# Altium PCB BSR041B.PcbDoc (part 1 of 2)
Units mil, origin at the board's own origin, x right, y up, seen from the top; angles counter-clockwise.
Board outline 3820.03 x 2030.03 mil, 4 copper layers (Top Layer, MidLayer1, MidLayer2, Bottom Layer), stack 59.4 mil thick; 65 components, 15 nets, 109 pads, 61 vias.
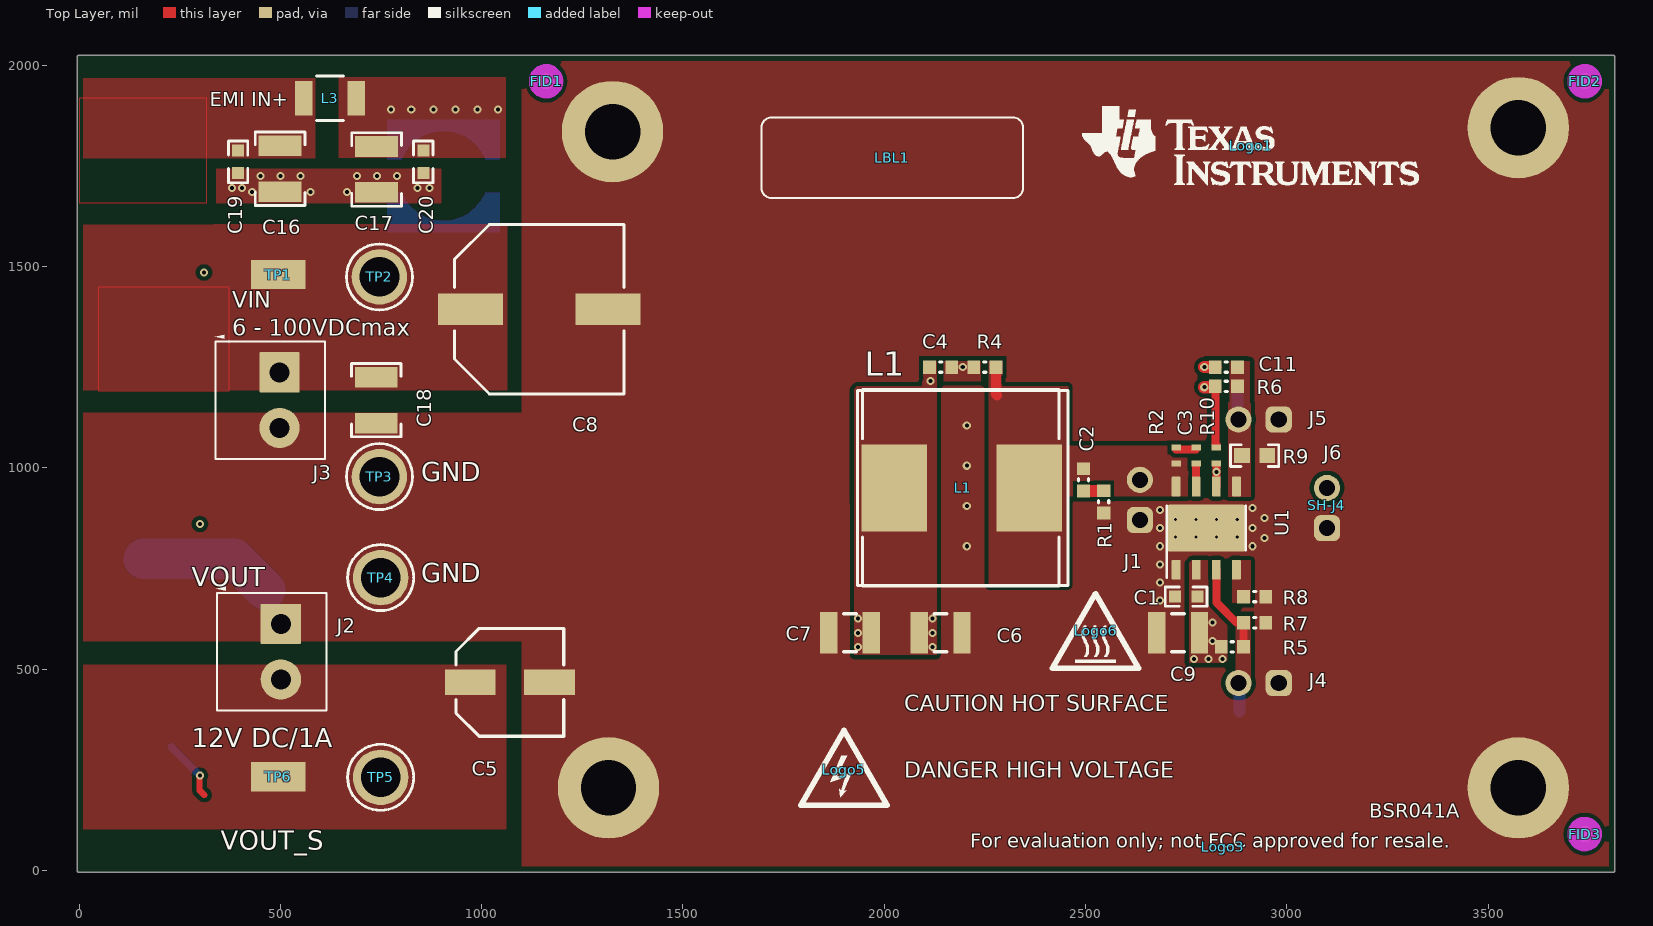
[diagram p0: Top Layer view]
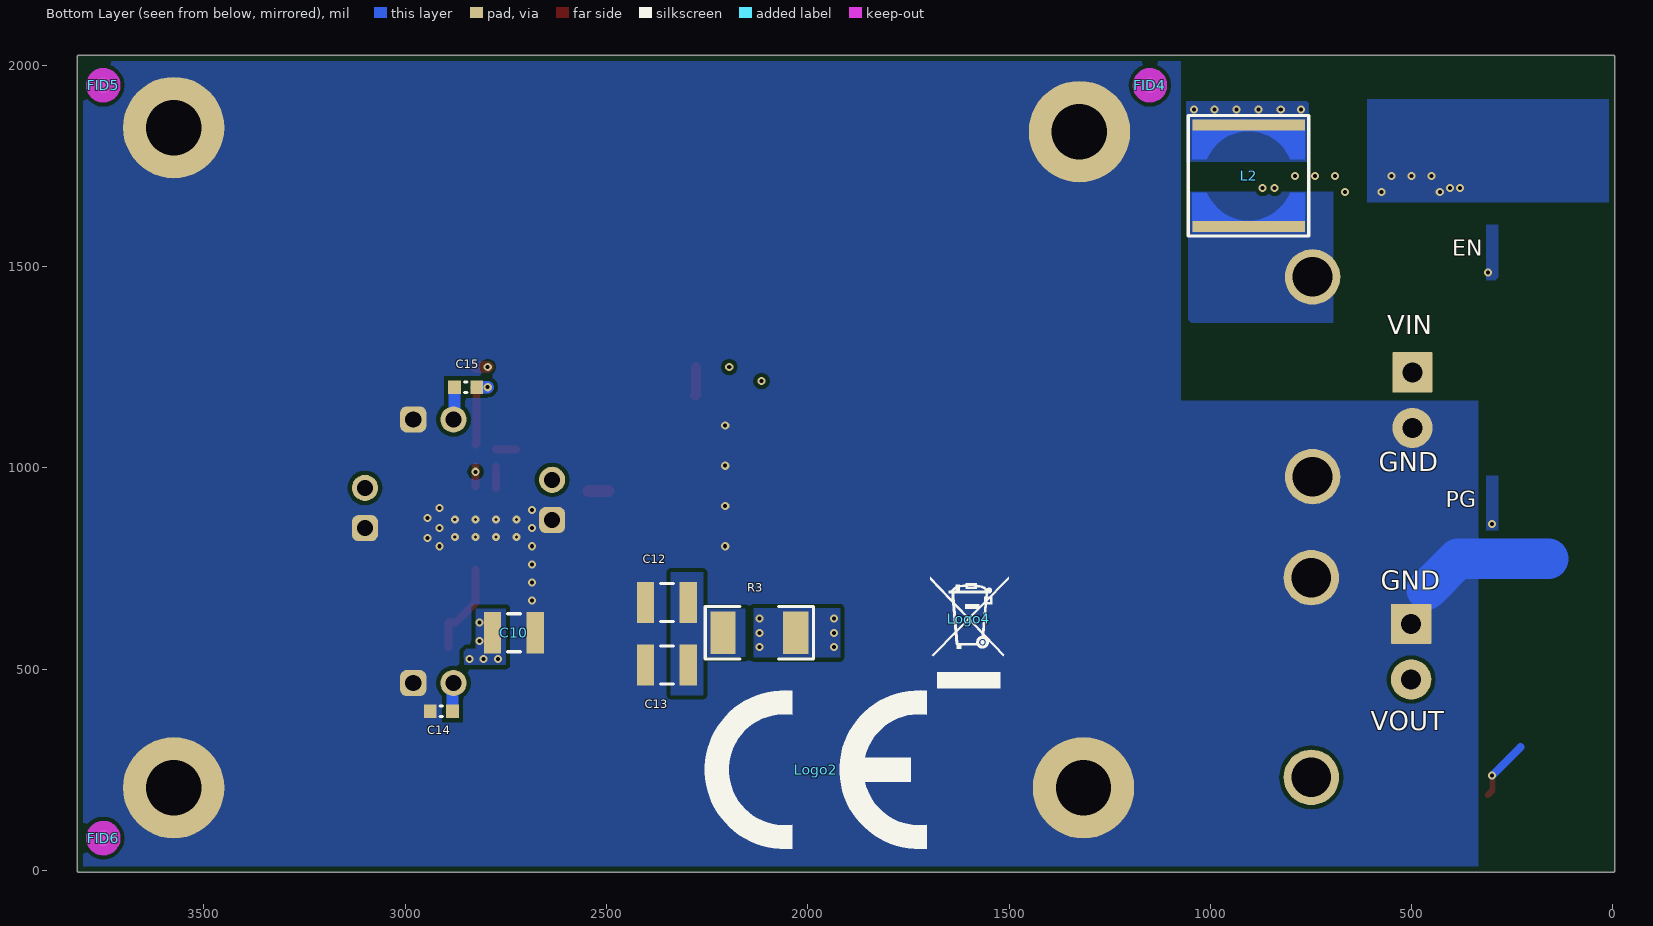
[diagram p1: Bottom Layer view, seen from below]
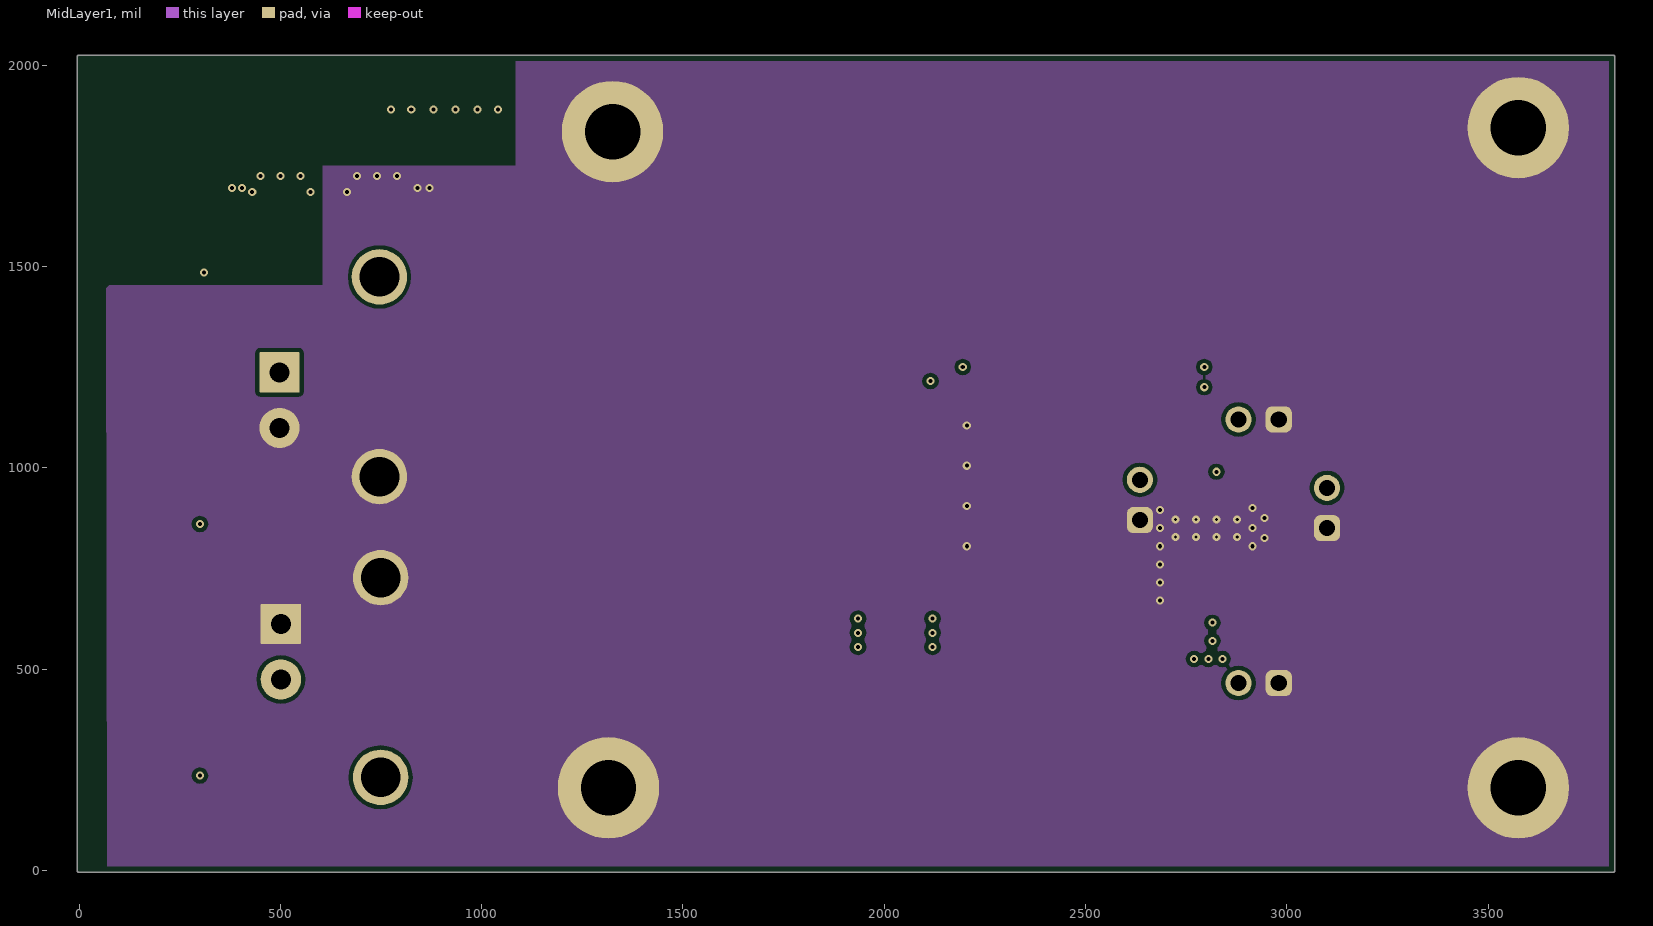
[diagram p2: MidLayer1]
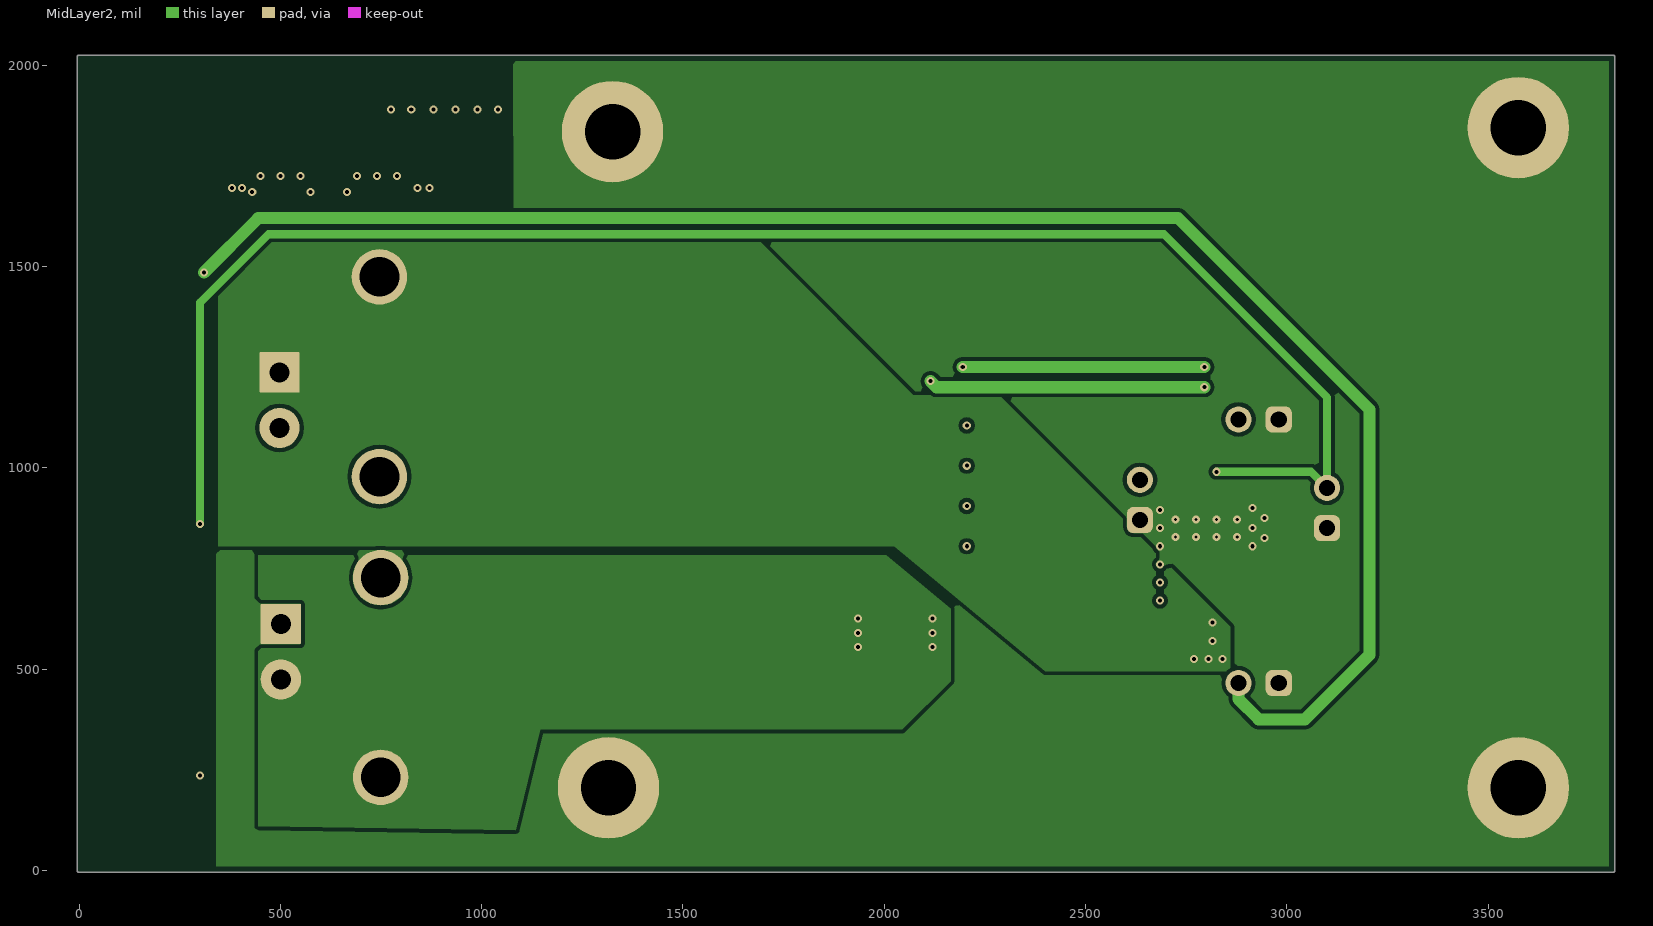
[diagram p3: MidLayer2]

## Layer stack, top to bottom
Top Solder: solder mask 0.4, Solder Resist, Dk 3.5
Top Layer: signal copper 2.8
Dielectric1: core 10, FR-4, Dk 4.8
MidLayer1: signal copper 1.4
Dielectric2: prepreg 31, FR-4, Dk 4.8
MidLayer2: signal copper 1.4
Dielectric3: core 10, FR-4, Dk 4.8
Bottom Layer: signal copper 2.8
Bottom Solder: solder mask 0.4, Solder Resist, Dk 3.5

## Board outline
0,-5.01 cw(c0,0) -5.02,0 -5.02,2020 cw(c0,2020) 0,2025.02 3810,2025.02 cw(c3810,2020) 3815.02,2020 3815.02,0 cw(c3810,0) 3810,-5.01 318,-5.01 cw(c318,0) 316.5,-4.79 cw(c315,0) 315,-5.01

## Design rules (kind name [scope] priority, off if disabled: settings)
AcuteAngle [All] p1: minimum=4.50000000000000E+0001 checktracksonly=TRUE
AssemblyTestPointUsage [All] p1: valid=2
BoardOutlineClearance BoardOutlineClearance_MountingHoles [OnCopper and InComponentClass('Mounting Holes')] p1: gap=40 ignorepadtopadclearanceinfootprint=FALSE
BoardOutlineClearance BoardOutlineClearance_Poly [OnCopper and IsPoly] p2: gap=15 ignorepadtopadclearanceinfootprint=FALSE
BoardOutlineClearance [OnCopper and Not InComponentClass('Logo') and not InComponentClass('FiducialMark') and not InRegion(1000,500,4000,800) and not InPoly] p3: gap=15 ignorepadtopadclearanceinfootprint=FALSE
Clearance Clearance_Keepouts [((IsTrack Or IsArc) And Not InPoly) And IsFree and IsKeepOut vs ((IsTrack Or IsArc) And Not InPoly) And IsFree and IsKeepOut] p1: gap=0 ignorepadtopadclearanceinfootprint=TRUE
Clearance Clearance_Poly [InPolygon] p2: gap=10 ignorepadtopadclearanceinfootprint=TRUE except(0: Arc-Hole Track-Hole SMDPad-Hole THPad-Hole Via-Hole Fill-Hole Poly-Hole Region-Hole Text-Hole)
Clearance Clearance_FiducialMark [IsKeepOut and InComponentClass('FiducialMark') vs IsPad and InComponentClass('FiducialMark')] p3: gap=0 ignorepadtopadclearanceinfootprint=TRUE
Clearance [All] p4: gap=5 ignorepadtopadclearanceinfootprint=TRUE except(0: Arc-Hole Track-Hole SMDPad-Hole THPad-Hole Via-Hole Fill-Hole Poly-Hole Region-Hole Text-Hole)
ComponentClearance ComponentClearance_MountingHoles_FiducialMarks [InComponentClass('Mounting Holes') vs InComponentClass('FiducialMark')] p1: gap=10 collisioncheckmode=3 verticalgap=10 showdistances=FALSE
ComponentClearance ComponentClearance_Shunt [InComponentClass('Header') vs InComponentClass('Shunt')] p2: gap=0 collisioncheckmode=3 verticalgap=0 showdistances=FALSE
ComponentClearance ComponentClearance_Logo [InComponentClass('Logo')] p3: gap=10 collisioncheckmode=3 verticalgap=10 showdistances=FALSE
ComponentClearance ComponentClearance_ScrewToNut [(HasFootprint('NY PMS 440 0025 PH')) vs (HasFootprint('Keystone_1902C'))] p4: gap=5 collisioncheckmode=3 verticalgap=10 showdistances=FALSE
ComponentClearance ComponentClearance_MountingHoles [InComponentClass('Mounting Holes')] p5: gap=10 collisioncheckmode=3 verticalgap=100000 showdistances=FALSE
ComponentClearance ComponentClearance_SmallPassives [HasFootprint('0201*') or HasFootprint('0402*') or HasFootprint('0508') or HasFootprint('0603*') or HasFootprint('0612') or HasFootprint('0805*') or HasFootprint('0815*') or HasFootprint('0830*') or HasFootprint('1206*') or HasFootprint('1210*') or HasFootprint('1808*') or HasFootprint('1812*') or HasFootprint('1825*') or HasFootprint('2010*') or HasFootprint('2220*') or HasFootprint('2225*') or HasFootprint('2512*') or HasFootprint('2728*') or HasFootprint('3518*') vs HasFootprint('0201*') or HasFootprint('0402*') or HasFootprint('0508') or HasFootprint('0603*') or HasFootprint('0612') or HasFootprint('0805*') or HasFootprint('0815*') or HasFootprint('0830*') or HasFootprint('1206*') or HasFootprint('1210*') or HasFootprint('1808*') or HasFootprint('1812*') or HasFootprint('1825*') or HasFootprint('2010*') or HasFootprint('2220*') or HasFootprint('2225*') or HasFootprint('2512*') or HasFootprint('2728*') or HasFootprint('3518*')] p6: gap=10 collisioncheckmode=3 verticalgap=10 showdistances=FALSE
ComponentClearance ComponentClearance_THtoSMT [IsThruComponent vs IsSMTComponent] p7: gap=10 collisioncheckmode=3 verticalgap=30 showdistances=FALSE
ComponentClearance ComponentClearance_THtoTH [IsThruComponent vs IsThruComponent] p8: gap=10 collisioncheckmode=3 verticalgap=30 showdistances=FALSE
ComponentClearance [All] p9: gap=10 collisioncheckmode=3 verticalgap=30 showdistances=FALSE
DiffPairsRouting [All] p1: maxlimit=100 minlimit=10 mostfreqgap=10 toplayer_minwidth=15 toplayer_maxwidth=15 toplayer_prefwidth=15 midlayer1_minwidth=15 midlayer1_maxwidth=15 midlayer1_prefwidth=15 midlayer2_minwidth=15 midlayer2_maxwidth=15 midlayer2_prefwidth=15 bottomlayer_minwidth=15 bottomlayer_maxwidth=15 bottomlayer_prefwidth=15 maxuncoupledlength=1000
FabricationTestPointUsage TestPointUsage [All] p1: valid=2 allowmultiple=FALSE
FabricationTestpoint Testpoint [All] p1: side=3 testpointundercomponent=TRUE minsize=40 maxsize=100 preferedsize=60 minholesize=0 maxholesize=40 preferedholesize=32 testpointgrid=1 allowsidetop=TRUE allowsidebottom=TRUE usegrid=TRUE gridtolerance=0.01
FanoutControl Fanout_LCC [IsLCC] p1: bgadir=Out bgaviamode=Centered fanoutstyle=Auto fanoutdirection=Alternating viagrid=1 // Fanout_LCC (Default Rule)
FanoutControl Fanout_BGA [IsBGA] p2: bgadir=Out bgaviamode=Centered fanoutstyle=Auto fanoutdirection=Alternating viagrid=1 // Fanout_BGA (Default Rule)
FanoutControl Fanout_Default [All] p4: bgadir=Out bgaviamode=Centered fanoutstyle=Auto fanoutdirection=Alternating viagrid=1 // Fanout_Default (Default Rule)
FanoutControl Fanout_Small [(CompPinCount < 5)] p5: bgadir=Out bgaviamode=Centered fanoutstyle=Auto fanoutdirection=OutThenIn viagrid=1 // Fanout_Small (Default Rule)
HoleSize [All] p1: absolutevalues=TRUE maxlimit=251 minlimit=7.87 maxpercent=80.000 minpercent=20.000
MinimumAnnularRing MinimumAnnularRing_ThermalPadVias [IsVia and InAnyComponent] p1: minimumring=5
MinimumAnnularRing [All] p2: minimumring=5
MinimumSolderMaskSliver MinimumSolderMaskSliver_Logo [InComponentClass('Logo') vs InComponentClass('Logo')] p1: minsoldermaskwidth=0.7
MinimumSolderMaskSliver [All] p2: minsoldermaskwidth=3.94
PlaneClearance PlaneClearance_1 [OnLayer('Top Layer')] p1: clearance=7.87
PlaneClearance [All] p2: clearance=9.84
PlaneConnect PlaneConnect_via [IsVia] p1: planeconnectstyle=Direct reliefexpansion=20 reliefentries=4 reliefconductorwidth=10 reliefairgap=10
PlaneConnect [All] p2: planeconnectstyle=Direct reliefexpansion=10 reliefentries=4 reliefconductorwidth=10 reliefairgap=10
PolygonConnect PolygonConnect_tp [(InComponent('TP*') or InComponent('J4*') or InComponent('J3*') or InComponent('X7') or InComponent('X9'))] p1: connectstyle=Direct reliefconductorwidth=10 reliefentries=4 polygonreliefangle="90 Angle" airgapwidth=10
PolygonConnect PolygonConnect_logo [InComponent('Logo1')] p2: connectstyle=Direct reliefconductorwidth=10 reliefentries=4 polygonreliefangle="90 Angle" airgapwidth=10
PolygonConnect PolygonConnect_Via [IsVia] p3: connectstyle=Direct reliefconductorwidth=10 reliefentries=4 polygonreliefangle="90 Angle" airgapwidth=10
PolygonConnect PolygonConnect_1 [HasFootprint('HARWIN_S1911-46R')] p4: connectstyle=Direct reliefconductorwidth=39.37 reliefentries=4 polygonreliefangle="90 Angle" airgapwidth=7.87
PolygonConnect PolygonConnect_poly [IsPoly] p5: connectstyle=Direct reliefconductorwidth=30 reliefentries=4 polygonreliefangle="90 Angle" airgapwidth=8
PolygonConnect [All] p6: connectstyle=Relief reliefconductorwidth=30 reliefentries=4 polygonreliefangle="90 Angle" airgapwidth=8
RoutingVias ThermalPadVias [IsVia and InAnyComponent] p1: holewidth=7.87 width=19.68 viastyle="Through Hole" minholewidth=7.87 minwidth=19.68 maxholewidth=12.99 maxwidth=23.62
RoutingVias [All] p2: holewidth=16 width=34 viastyle="Through Hole" minholewidth=7 minwidth=20 maxholewidth=40 maxwidth=65
SilkToSilkClearance SilkToSilkClearance_Pb-FreeLogo [(HasFootprint('Pb-Free_Overlay_Medium') OR HasFootprint('Pb-Free_Overlay_Small')) vs (HasFootprint('Pb-Free_Overlay_Medium') OR HasFootprint('Pb-Free_Overlay_Small'))] p1: silktosilkclearance=0
SilkToSilkClearance [All] p2: silktosilkclearance=3
SilkToSolderMaskClearance SilkToComponentPadClearance [(IsPad or IsFill or IsRegion) and InAnycomponent] p1: minsilkscreentomaskgap=5 clearancetoexposedcopper=TRUE
SilkToSolderMaskClearance "Silk to Solder Mask Opening" [All] p2: minsilkscreentomaskgap=4 clearancetoexposedcopper=FALSE
SolderMaskExpansion [All] p1: expansion=1.97
Width [All] p1: maxlimit=100 minlimit=6 preferedwidth=10 checkconnectedcopper=TRUE
15 further rules are at their usual default settings.

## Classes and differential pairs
component class Label: LBL1
component class Shunt: SH-J4
component class BSR041B: 30 500kHz C1 C2 C3 C4 C5 C6 C7 C8 C9 C10 C11 C12 C13 C14 C15 C16 C17 C18 C19 C20 CIN1 COUT2 COUT3 gnd J1 J2 J3 J4 J5 J6 L1 L2 L3 R1 R2 R3 R4 R5 R6 R7 R8 R9 R10 TP1 TP2 TP3 TP4 TP5 TP6 TPCLK180 U1 vin Vout
component class AssemblyNote: ZZ1 ZZ2 ZZ3 ZZ4
component class BSR041B_Hardware: !PCB FID1 FID2 FID3 FID4 FID5 FID6 LBL1 Logo1 Logo2 Logo3 Logo4 Logo5 Logo6 SH-J4 ZZ1 ZZ2 ZZ3 ZZ4
component class Logo: Logo1
component class Header: J1 J4 J5 J6
component class FiducialMark: FID1 FID2 FID3 FID4 FID5 FID6

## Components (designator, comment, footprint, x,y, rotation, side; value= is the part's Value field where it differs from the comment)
C1 "HMK107B7104KAHT" 0603_HV 2750,680 r0 top value=0.1uF
C2 "CGA3E2X7R2A102K080AA" 0603L 2495,970 r270 top value=1000pF
C3 "GCM155R71H222KA37D" 0402S 2775,1030 r270 top value=2200pF
C4 "CR" 0603L 2140,1250 r0 top value=3300pF
C5 "COUT_BULK" Panasonic_D8 1070,467 r0 top value=100uF
C6 "GRT32ER61E226KE13L" 1210_270L 2140,590 r0 top value=22uF
C7 "GRT32ER61E226KE13L" 1210_270L 1915,590 r180 top value=22uF
C8 "CIN_BULK" SM_RADIAL_G 1143,1394 r0 top value=33uF
C9 "CGA6N3X7R2A225K230AB" 1210_250L 2730,590 r0 top value=2.2uF
C10 "CGA6N3X7R2A225K230AB" 1210_250L 2730,590 r0 bottom value=2.2uF
C11 "C0603C560J5GACTU" 0603L 2850,1250 r0 top value=56pF
C12 "COUT3" 1210_270L 2350,665 r0 bottom value=22uF
C13 "COUT4" 1210_270L 2350,510 r0 bottom value=22uF
C14 "CEN" 0603L 2910,395 r0 bottom value=0.01uF
C15 "CFF" 0603L 2850,1200 r0 bottom value=1000pF
C16 "CGA6M3X7S2A475K200AB" 1210_220 499,1743 r270 top value=4.7uF
C17 "CGA6M3X7S2A475K200AB" 1210_220 739,1741 r270 top value=4.7uF
C18 "CGA6M3X7S2A475K200AB" 1210_220 738,1168 r270 top value=4.7uF
C19 "HMK107B7104KAHT" 0603_HV 395,1760 r270 top value=0.1uF
C20 "HMK107B7104KAHT" 0603_HV 855,1760 r270 top value=0.1uF
FID1 "Fiducial" Fiducial10-20 1160,1960 r90 top
FID2 "Fiducial" Fiducial10-20 3740,1960 r90 top
FID3 "Fiducial" Fiducial10-20 3740,90 r90 top
FID4 "Fiducial" Fiducial10-20 1150,1950 r90 bottom
FID5 "Fiducial" Fiducial10-20 3750,1950 r90 bottom
FID6 "Fiducial" Fiducial10-20 3750,80 r90 bottom
J1 "TSW-102-07-G-S" TSW-102-07-G-S 2635,920 r90 top
J2 "ED555/2DS" TERM_BLK_ED555-2DS 501,612 r270 top
J3 "ED555/2DS" TERM_BLK_ED555-2DS 498,1237 r270 top
J4 "TSW-102-07-G-S" TSW-102-07-G-S 2930,465 r180 top
J5 "TSW-102-07-G-S" TSW-102-07-G-S 2930,1120 r180 top
J6 "TSW-102-07-G-S" TSW-102-07-G-S 3100,900 r90 top
L1 "MSS1246T-683MLB" MSS1246T 2195,950 r180 top value=68uH
L1 "MSS1260-124KLB" MSS1260 2190,950 r180 top value=120uH
L2 "MSS7341T-153MLB" MSS7341 905,1725 r270 bottom value=15uH
L3 "FBMH3225HM202NT" 1210_280 623,1918 r0 top value="2000 ohm"
LBL1 "THT-14-423-10" Label_650x200 2020,1770 r180 top
Logo1 "Texas Instruments" TI_Stacked_Overlay_Small 2910,1800 r0 top
Logo2 "CE Mark" CE_Mark_10mm 1980,250 r180 bottom
Logo3 "FCC disclaimer" FCC_disclaimer 2841,58 r0 top
Logo4 "WEEE logo" WEEE_Minimum 1600,625 r180 bottom
Logo5 "DANGER HIGH VOLTAGE" IEC_HighVoltage_Small 1900,250 r0 top
Logo6 "CAUTION HOT SURFACE" IEC_HotSurface_Small 2525,595 r0 top
R1 "CRCW06031R00JNEA" 0603L 2545,915 r90 top value=1.0
R2 "RBST" 0402S 2725,1030 r270 top value=0
R3 "DNP" 2010 2120,590 r180 bottom value=0.2
R4 "RC0603FR-07453KL" 0603L 2250,1250 r180 top value=453k
R5 "RC0603FR-071ML" 0603L 2865,555 r180 top value=1.00Meg
R6 "RC0603FR-07453KL" 0603L 2850,1202 r180 top value=453k
R7 "RC0603FR-07332KL" 0603L 2920,615 r180 top value=332k
R8 "RG1608P-1053-B-T5" 0603L 2920,680 r180 top value=105k
R9 "RG1608P-4992-B-T5" 0603 2920,1030 r180 top value=49.9k
R10 "ERJ-2RKF1003X" 0402S 2825,1030 r90 top value=100k
SH-J4 "SNT-100-BK-G" SNT-100-BK-G 3098.63,907.33 r90 top value=1x2
TP1 "S1751-46" Harwin_S1751-46 495,1480 r0 top
TP2 "" Keystone1598-2 746,1474 r90 top value=Triple
TP3 "" Keystone1598-2 746,978 r90 top value=Triple
TP4 "" Keystone1598-2 749,727 r90 top value=Triple
TP5 "" Keystone1598-2 749,231 r90 top value=Triple
TP6 "S1751-46" Harwin_S1751-46 495,232 r180 top
U1 "LM5164QDDARQ1" DDA0008E_L 2800,850 r90 top
ZZ1 "This Assembly Note is for PCB labels only" AssemblyNoteLabel 4520,-510 r0 top
ZZ2 "These assemblies are ESD sensitive, ESD precautions shall be observed." AssemblyNote 4520,-420 r0 top
ZZ3 "These assemblies must be clean and free from flux and all contaminants. Use of no clean flux is not acceptable." AssemblyNote 4530,-340 r0 top
ZZ4 "These assemblies must comply with workmanship standards IPC-A-610 Class 2, unless otherwise specified." AssemblyNote 4530,-270 r0 top

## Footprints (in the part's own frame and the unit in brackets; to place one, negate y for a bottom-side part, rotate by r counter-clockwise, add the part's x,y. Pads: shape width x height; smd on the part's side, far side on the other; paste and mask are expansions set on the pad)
0402S [mil] "Based on C0402S footprint from PADS legacy"
  rect 15x24 smd: 1(-20,0) 2(20,0)
  body extent -22,-12 22,12, height 24
0603 [mm] "0603 from SM-752 data"
  rect 1x0.95 smd: 1(-0.8,0) 2(0.8,0)
  silkscreen extent -1.52,-0.69 1.52,0.69, body extent -0.87,-0.47 0.87,0.47, height 1
0603_HV [mil] "Ernesto recommended land pattern.  26 mil between pads."
  rect 30x30 smd: 1(-28,0) 2(28,0)
  silkscreen extent -52,-24 52,24, body extent -34,-19 34,19, height 39
0603L [mm] "0603 from SM-752 data"
  rect 0.8x0.85 smd: 1(-0.7,0) 2(0.7,0)
  silkscreen extent -0.07,-0.33 0.07,0.33, body extent -0.87,-0.47 0.87,0.47, height 1
1210_220 [mm] "1210"
  rect 1.3x2.7 smd: 1(-1.45,0) 2(1.45,0)
  silkscreen extent -2.32,-1.57 2.32,1.57, body extent -1.7,-1.35 1.7,1.35, height 2.2
1210_250L [mm] "1210"
  rect 1.1x2.6 smd: 1(-1.35,0) 2(1.35,0)
  silkscreen extent -0.4,-1.2 0.4,1.2, body extent -1.7,-1.35 1.7,1.35, height 2.5
1210_270L [mm] "1210"
  rect 1.1x2.6 smd: 1(-1.35,0) 2(1.35,0)
  silkscreen extent -0.4,-1.2 0.4,1.2, body extent -1.7,-1.35 1.7,1.35, height 2.7
1210_280 [mm] "SMD, 2-Leads, Body 3.6x2.8mm, Height 2.8mm"
  rect 1.1x2.2 smd: 1(-1.65,0) 2(1.65,0)
  silkscreen extent -0.84,-1.4 0.84,1.4, body extent -1.8,-1.4 1.8,1.4, height 2.8
2010 [mm] "Chip Capacitor, Body 5.08x2.54mm, IPC Medium Density"
  rect 1.6x2.7 smd: 1(-2.3,0) 2(2.3,0)
  silkscreen extent -3.42,-1.65 3.42,1.65, body extent -2.73,-1.45 2.73,1.45, height 1.66
AssemblyNote [mil] "Assembly Note"
AssemblyNoteLabel [mil] "Assembly Note for PCB Labels"
CE_Mark_10mm [mil] "Double the minimum text height for CE Mark"
  silkscreen extent -275,-197 276,197
DDA0008E_L [mm]
  rrect18% 1.25x0.55 smd: 1(-2.625,1.905) 2(-2.625,0.635) 3(-2.625,-0.635) 4(-2.625,-1.905) 5(2.625,-1.905) 6(2.625,-0.635) 7(2.625,0.635) 8(2.625,1.905)
  rrect7% 2.95x4.9 smd paste-1.5 mask-1.5: 9(0,0)
  rrect4% 2.4x3.1 on Top Paste: 9(0,0)
  rrect4% 2.4x3.1 on Top Solder: 9(0,0)
  silkscreen extent -3.13,-2.5 1.4,2.5, body extent -3,-2.45 3,2.45, height 1.57
FCC_disclaimer [mil]
Fiducial10-20 [mm]
  round 1 smd mask+0.5: 1(0,0)
  Top Layer keep-out circle w1.178: c0,0 r0.5
Harwin_S1751-46 [mm] "Test Point, Body 3.25x1.65mm"
  rect 3.45x1.85 smd: 1(0,0)
  body extent -1.62,-0.82 1.63,0.82, height 2.05
IEC_HighVoltage_Small [mil]
  silkscreen extent -107,-88 107,97
IEC_HotSurface_Small [mil]
  silkscreen extent -107,-93 107,92
Keystone1598-2 [mm] "Triple Turret"
  round 3.5 hole 2.5: 1(0,0)
  silkscreen extent -2.08,-2.08 2.08,2.08, body extent -1.6,-1.6 1.59,1.6, height 7.72
Label_650x200 [mil] "Thermal Transfer Label"
  round 1 on Mech13: 0(0,0)
  silkscreen extent -325,-100 325,100, body extent -325,-100 325,100, height 1
MSS1246T [mm] "Recommended land pattern for Coilcraft MSS1246T series Document 540-2 rev 10/15/08"
  rect 4x5.5 smd: 1(-4.25,0) 2(4.25,0)
  silkscreen extent -6.64,-6.14 6.63,6.16, body extent -6.15,-6.15 6.15,6.15, height 4.8
MSS1260 [mm]
  rect 4x5.5 smd: 1(-4.25,0) 2(4.25,0)
  silkscreen extent -6.2,-6.2 6.2,6.2, body extent -6.15,-6.15 6.15,6.15, height 6.25
MSS7341 [mm] "Coilcraft recommended land pattern Document 383-2 1/3/11"
  rect 0.7x7.1 smd: 1(-3.2,0) 2(3.2,0)
  Top Layer region: 1.05,3.55 3.55,3.55 3.55,-3.55 1.05,-3.55 1.05,-2.623 2.135,-1.85 2.745,-0.666 2.745,0.666 2.135,1.85 1.05,2.623 1.05,2.623
  Top Layer region: -1.05,3.55 -3.55,3.55 -3.55,-3.55 -1.05,-3.55 -1.05,-2.623 -2.135,-1.85 -2.745,-0.666 -2.745,0.666 -2.135,1.85 -1.05,2.623 -1.05,2.623
  silkscreen extent -3.8,-3.8 3.8,3.8, body extent -3.78,-3.78 3.78,3.78, height 4.12
Panasonic_D8 [mm] "SMD, 2-Leads, Dia 6.3mm"
  rect 3.2x1.6 smd: 1(-2.5,0) 2(2.5,0)
  silkscreen extent -3.4,-3.4 3.4,3.4, body extent -3.4,-3.4 3.4,3.4, height 8.01
SM_RADIAL_G [mm] "10 x 10.2mm:  Panasonic G"
  rect 4.1x2 smd: 1(-4.35,0) 2(4.35,0)
  silkscreen extent -5.35,-5.35 5.35,5.35, body extent -5.25,-5.25 5.25,5.25, height 10.5
SNT-100-BK-G [mil] "Samtec STEP model"
  round 1 on Mech3: 0(0,0)
  body extent -100,-50 100,50, height 344
TERM_BLK_ED555-2DS [mil]
  rrect4% 100x100 hole 50: 1(0,0)
  round 100 hole 50: 2(138,0)
  silkscreen extent -93,-161 215,113, body extent -69,-150 207,106, height 323
TI_Stacked_Overlay_Small [mil]
  silkscreen extent -418,-98 418,98
TSW-102-07-G-S [mm] "Samtec 100mil, 1x2, 230 mil above insulator"
  rrect50% 1.65x1.65 hole 1.016: 1(-1.27,0)
  round 1.65 hole 1.016: 2(1.27,0)
  body extent -2.54,-1.27 2.54,1.27, height 8.38
WEEE_Minimum [mil] "WEEElie bin"
  silkscreen extent -95,-172 99,104

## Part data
C1 C19 C20: library part CMP-0081011-1, "CAP, CERM, 0.1 µF, 100 V,+/- 10%, X7R, AEC-Q200 Grade 1, 0603", Cap_Case=0603, Manufacturer="Taiyo Yuden", Supplier Part Number 1=587-6009-1-ND, TempCo=X7R, Tolerance_%=10%, Value2=100V, ValueDisplayed=0.1µF
C2: library part CMP-0007081-4, "CAP, CERM, 1000 pF, 100 V, +/- 10%, X7R, AEC-Q200 Grade 1, 0603", Cap_Case=0603, Manufacturer=TDK, Supplier Part Number 1=445-5806-1-ND, TempCo=X7R, Tolerance_%=10%, Value1="1.97137 ohm", Value2=100V, ValueDisplayed=1000pF
C3: library part CMP-0006357-2, "CAP, CERM, 2200 pF, 50 V, +/- 10%, X7R, AEC-Q200 Grade 1, 0402", Cap_Case=0402, Manufacturer=MuRata, Supplier Part Number 1=490-4914-1-ND, TempCo=X7R, Tolerance_%=10%, Value1=Unknown, Value2=50V, ValueDisplayed=2200pF
C4: library part CMP-0007087-4, "CAP, CERM, 3300 pF, 100 V, +/- 10%, X7R, AEC-Q200 Grade 1, 0603", Cap_Case=0603, Manufacturer=TDK, PartNumber=CGA3E2X7R2A332K080AA, Supplier Part Number 1=445-5809-1-ND, TempCo=X7R, Tolerance_%=10%, Value1="0.662155 ohm", Value2=100V, ValueDisplayed=3300pF
C5: library part CMP-0011205-2, "CAP, AL, 100 uF, 50 V, +/- 20%, 0.34 ohm, AEC-Q200 Grade 2, SMD", Cap_Case=6.3x7.7mm, Manufacturer=Panasonic, PartNumber=EEEFTH101XAP, Supplier Part Number 1=PCE5024CT-ND, Tolerance_%=20%, Value1="0.34 ohm", Value2=50V, ValueDisplayed=100uF
C6 C7: library part CMP-0084059-1, "CAP, CERM, 22 µF, 25 V,+/- 10%, X5R, AEC-Q200 Grade 3, 1210", Cap_Case=1210, Manufacturer=MuRata, TempCo=X5R, Tolerance_%=10%, Value2=25V, ValueDisplayed=22µF
C8: library part CMP-0011203-2, "CAP, AL, 33 uF, 100 V, +/- 20%, 0.7 ohm, AEC-Q200 Grade 2, SMD", Cap_Case=G, Manufacturer=Panasonic, PartNumber=EEE-FK2A330P, Supplier Part Number 1=PCE3846CT-ND, Tolerance_%=20%, Value1="0.7 ohm", Value2=100V, ValueDisplayed=33uF
C9 C10: library part CMP-0009152-2, "CAP, CERM, 2.2 uF, 100 V, +/- 10%, X7R, AEC-Q200 Grade 1,", Cap_Case=1210_250, Manufacturer=TDK, Supplier Part Number 1=445-5866-1-ND, TempCo=X7R, Tolerance_%=10%, Value1="0.00173 ohm", Value2=100V, ValueDisplayed=2.2uF
C11: library part CMP-0006952-4, "CAP, CERM, 56 pF, 50 V, +/- 5%, C0G/NP0, 0603", Cap_Case=0603, Manufacturer=Kemet, Supplier Part Number 1=399-1057-1-ND, TempCo=C0G/NP0, Tolerance_%=5%, Value1=Unknown, Value2=50V, ValueDisplayed=56pF
C12 C13: library part CMP-0009255-2, "CAP, CERM, 22 uF, 25 V, +/- 10%, X7R, AEC-Q200 Grade 1, 1210", Cap_Case=1210, Manufacturer="Taiyo Yuden", PartNumber=TMK325B7226KMHT, Supplier Part Number 1=587-4337-1-ND, TempCo=X7R, Tolerance_%=10%, Value1=Unknown, Value2=25V, ValueDisplayed=22uF
C14: library part CMP-0080063-1, "CAP, CERM, 0.01 µF, 100 V,+/- 10%, X8R, AEC-Q200 Grade 0, 0603", Cap_Case=0603, Manufacturer=TDK, PartNumber=CGA3E2X8R2A103K080AD, Supplier Part Number 1=445-8825-1-ND, TempCo=X8R, Tolerance_%=10%, Value2=100V, ValueDisplayed=0.01µF
C15: library part CMP-0006844-4, "CAP, CERM, 1000 pF, 50 V, +/- 5%, X7R, AEC-Q200 Grade 1, 0603", Cap_Case=0603, Manufacturer=Kemet, PartNumber=C0603C102J5RACAUTO, Supplier Part Number 1=399-12989-1-ND, TempCo=X7R, Tolerance_%=5%, Value1=Unknown, Value2=50V, ValueDisplayed=1000pF
C16 C17 C18: library part CMP-0009150-2, "CAP, CERM, 4.7 uF, 100 V, +/- 10%, X7S, AEC-Q200 Grade 1, 1210", Cap_Case=1210_220, Manufacturer=TDK, Supplier Part Number 1=445-7005-1-ND, TempCo=X7S, Tolerance_%=10%, Value1="0.004236 ohm", Value2=100V, ValueDisplayed=4.7uF
FID1 FID2 FID3 FID4 FID5 FID6: library part CMP-0077181-1, "Fiducial mark.  There is nothing to buy or mount.", Manufacturer=N/A
J1 J4 J5 J6: library part CMP-0075405-2, "Header, 100mil, 2x1, Gold, TH", Color=Black, Current_A=6.3A, Manufacturer=Samtec, Supplier Part Number 1=SAM1029-02-ND, Voltage_V=550V
J2 J3: library part CMP-0074913-1, "Terminal Block, 3.5mm Pitch, 2x1, TH", Color=Grey, Current_A=6A, Manufacturer="On-Shore Technology", Supplier Part Number 1=ED1514-ND, Voltage_V=150V
L1: library part CMP-0061481-2, "Inductor, Shielded Drum Core, Ferrite, 68 uH, 1.8 A, 0.17 ohm, SMD", Manufacturer=Coilcraft, Value1="0.17 ohm", Value2=1.8A, ValueDisplayed=68uH
L1: library part CMP-0061895-2, "Inductor, Shielded Drum Core, Ferrite, 120 uH, 1.85 A, 0.19 ohm, SMD", Manufacturer=Coilcraft, Value1="0.19 ohm", Value2=1.85A, ValueDisplayed=120uH
L2: library part CMP-0061601-2, "Inductor, Shielded Drum Core, Ferrite, 15 uH, 1.8 A, 0.05 ohm, AEC-Q200 Grade 1, SMD", Manufacturer=Coilcraft, Value1="0.05 ohm", Value2=1.8A, ValueDisplayed=15uH
L3: library part CMP-0003373-1, "Ferrite Bead, 2000 ohm @ 100 MHz, 1.2 A, 1210", Manufacturer="Taiyo Yuden", Supplier Part Number 1=587-1754-1-ND, Value1="0.13 ohm", Value2=1.2A, ValueDisplayed="2000 ohm"
LBL1: library part CMP-0003625-1, "Thermal Transfer Printable Labels, 0.650\" W x 0.200\" H - 10,000 per roll", Manufacturer=Brady, Supplier Part Number 1=97C5133
Logo1: library part CMP-0074838-1, "Texas Instrument Corporate Signature"
Logo2: library part CMP-0074844-1
Logo3: library part CMP-0074847-1, "FCC_disclaimer"
Logo4: library part CMP-0074769-1
Logo5: library part CMP-0074835-1, "IEC 61010-1 High Voltage Warning"
Logo6: library part CMP-0074837-1, "IEC 61010-1 Hot Surface Warning"
R1: library part CMP-0025743-4, "RES, 1.0, 5%, 0.1 W, AEC-Q200 Grade 0, 0603", Manufacturer=Vishay-Dale, Power_W=100mW, Supplier Part Number 1=541-1.0GCT-ND, TempCo="200 ppm/C", Tolerance_%=5%, Value2=0.1W, Value_Code=1R00, ValueDisplayed=1.0
R2: library part CMP-0026822-3, "RES, 0, 5%, 0.063 W, AEC-Q200 Grade 0, 0402", Manufacturer=Vishay-Dale, PartNumber=CRCW04020000Z0ED, Power_W=63mW, Supplier Part Number 1=541-0.0JCT-ND, TempCo="200 ppm/C", Tolerance_%=5%, Value2=0.063W, Value_Code=0000, ValueDisplayed=0
R3: library part CMP-0016525-2, "RES, 0.2, 1%, 1 W, 2010", Manufacturer="Stackpole Electronics Inc", PartNumber=CSRN2010FKR200, Power_W=1W, Supplier Part Number 1=CSRN2010FKR200CT-ND, TempCo="250 ppm/C", Tolerance_%=1%, Value_Code=R200, ValueDisplayed=0.2
R4 R6: library part CMP-0023120-4, "RES, 453 k, 1%, 0.1 W, 0603", Manufacturer=Yageo, Power_W=100mW, Supplier Part Number 1=311-453KHRCT-ND, TempCo="100 ppm/C", Tolerance_%=1%, Value2=0.1W, Value_Code=453k
R5: library part CMP-0022899-4, "RES, 1.00 M, 1%, 0.1 W, 0603", Manufacturer=Yageo, Power_W=100mW, Supplier Part Number 1=311-1.00MHRCT-ND, TempCo="100 ppm/C", Tolerance_%=1%, Value2=0.1W, Value_Code=1M00, ValueDisplayed=1.00M
R7: library part CMP-0023034-4, "RES, 332 k, 1%, 0.1 W, 0603", Manufacturer=Yageo, Power_W=100mW, Supplier Part Number 1=311-332KHRCT-ND, TempCo="100 ppm/C", Tolerance_%=1%, Value2=0.1W, Value_Code=332k
R8: library part CMP-0023408-3, "RES, 105 k, 0.1%, 0.1 W, 0603", Manufacturer="Susumu Co Ltd", Power_W=100mW, Supplier Part Number 1=RG16P105KBCT-ND, TempCo="25 ppm/C", Tolerance_%=0.1%, Value2=0.1W, Value_Code=105k
R9: library part CMP-0023563-3, "RES, 49.9 k, 0.1%, 0.1 W, 0603", Manufacturer="Susumu Co Ltd", Power_W=100mW, Supplier Part Number 1=RG16P49.9KBCT-ND, TempCo="25 ppm/C", Tolerance_%=0.1%, Value2=0.1W, Value_Code=49k9, ValueDisplayed=49.9k
R10: library part CMP-0026659-1, "RES, 100 k, 1%, 0.1 W, 0402", Manufacturer=Panasonic, Power_W=100mW, TempCo="100 ppm/C", Tolerance_%=1%, Value2=0.1W, Value_Code=100k
SH-J4: library part CMP-0003623-1, "Shunt, 100mil, Gold plated, Black", Alternate Manufacturer=3M, Alternate PartNumber=969102-0000-DA, Manufacturer=Samtec, Supplier Part Number 1=SNT-100-BK-G-ND
TP1 TP6: library part CMP-0075188-1, "Test Lead clips and hooks, SMT", Current_A=2A, Manufacturer=Harwin, Supplier Part Number 1=S1751-46-ND
TP2 TP3 TP4 TP5: library part 1598-2, "Terminal, Turret, TH, Triple", Manufacturer=Keystone, Supplier Part Number 1=1598-2K-ND
U1: library part CMP-0080796-1, "100-V Low IQ Synchronous Buck Regulator, DDA0008E (SOIC-8)", Alternate Manufacturer="Texas Instruments", Alternate PartNumber=LM5164QDDATQ1
ZZ1: library part CMP-0003616-3
ZZ2: library part CMP-0077236-1
ZZ3: library part CMP-0077237-1
ZZ4: library part CMP-0077238-1

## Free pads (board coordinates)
  round 251.97 hole 137.8: 1(1315,205) 1(1325,1835) 1(3575,205) 1(3575,1845)

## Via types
v1: diameter 20, hole 10, Top Layer to Bottom Layer, tented both sides, 53 vias
v2: diameter 19.68, hole 7.87, Top Layer to Bottom Layer, tented both sides, 4 vias
v3: diameter 19.68, hole 7.87, Top Layer to Bottom Layer, 4 vias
